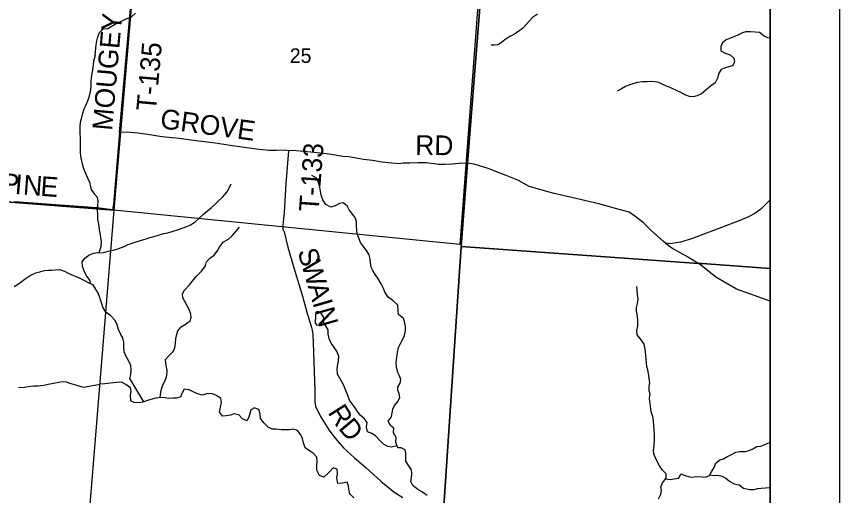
# Model space of a CAD drawing. Extents: x 0 to 42.5, y 0 to 22.
# Drawn here: x 7.815 to 9, y 18.727 to 19.417 of the extents above; entities that cross this region are included whole.
import ezdxf

# ---------------------------------------------------------------- set-up
doc = ezdxf.new("R2010")
doc.units = 0
for name, color, linetype in [('GM_X_County_Road', 7, 'Continuous'), ('GM_X_Interchange_Ramps', 7, 'Continuous'), ('GM_X_Minor_Lake', 7, 'Continuous'), ('GM_X_Minor_River', 7, 'Continuous'), ('GM_X_Section', 7, 'Continuous'), ('GM_X_Section_Text', 7, 'Continuous'), ('GM_X_Township_Road', 7, 'Continuous'), ('GM_X_Township_Road_Text', 7, 'Continuous'), ('SH_Cut_Line', 7, 'Continuous'), ('SH_Data', 7, 'Continuous')]:
    doc.layers.add(name, color=color, linetype=linetype)

msp = doc.modelspace()

# ---------------------------------------------------------------- linework, layer by layer
at = {"layer": 'GM_X_County_Road'}
msp.add_lwpolyline([(8.9, 19.0066), (8.8518, 19.0239), (8.8221, 19.0415), (8.7973, 19.0609)], dxfattribs=at)
at = {"layer": 'GM_X_Interchange_Ramps'}
msp.add_lwpolyline([(8.9, 19.0538), (8.9, 20.9), (8.5977, 20.9), (8.5975, 20.897), (8.533, 20.1102), (8.5155, 19.8538), (8.4644, 19.2057), (8.4553, 19.0856), (8.7971, 19.0612), (8.8021, 19.0608)], close=True, dxfattribs=at)
for points in [[(7.6874, 18.6472), (7.929, 18.6269), (8.111, 18.6109), (8.2565, 18.5997), (8.2741, 18.602), (8.283, 18.6019), (8.295, 18.5988), (8.3015, 18.5957), (8.4216, 18.5836), (8.4225, 18.5968), (8.4553, 19.0856), (8.4644, 19.2057), (8.5155, 19.8538)], [(8.9, 15.5376), (8.9, 19.0538), (8.8021, 19.0608), (8.7971, 19.0612), (8.4553, 19.0856), (8.4225, 18.5968), (8.4216, 18.5836), (8.4123, 18.4784), (8.3832, 18.1485), (8.3379, 17.6339), (8.308, 17.2922), (8.3087, 17.2846), (8.3084, 17.2765), (8.3074, 17.2694), (8.2902, 17.0877), (8.2877, 17.0646), (8.2823, 16.9912), (8.274, 16.8923), (8.2572, 16.7056), (8.248, 16.5943), (8.2478, 16.5901), (8.1793, 15.7911)]]:
    msp.add_lwpolyline(points, dxfattribs=at)
at = {"layer": 'GM_X_Minor_Lake'}
for points in [[(8.2566, 18.9794), (8.2574, 18.9834), (8.2557, 18.9861), (8.2525, 18.9908), (8.2482, 18.9918), (8.2459, 18.9907), (8.2455, 18.9863), (8.245, 18.9752), (8.2476, 18.9723), (8.2505, 18.9726), (8.2539, 18.9747)], [(8.2539, 18.9747), (8.2566, 18.9794)]]:
    msp.add_lwpolyline(points, dxfattribs=at)
at = {"layer": 'GM_X_Minor_River'}
for p, q in [((8.8752, 18.7939), (8.881, 18.7971)), ((8.881, 18.7971), (8.8865, 18.798)), ((8.8865, 18.798), (8.8917, 18.7997)), ((8.8917, 18.7997), (8.8966, 18.8019)), ((8.8966, 18.8019), (8.9, 18.8033)), ((8.8378, 18.7823), (8.8433, 18.7855)), ((8.8433, 18.7855), (8.8509, 18.7892)), ((8.8509, 18.7892), (8.8562, 18.79)), ((8.8562, 18.79), (8.8643, 18.7903)), ((8.8643, 18.7903), (8.87, 18.7916)), ((8.87, 18.7916), (8.8752, 18.7939)), ((8.8193, 18.7673), (8.822, 18.7734)), ((8.822, 18.7734), (8.8277, 18.7781)), ((8.8277, 18.7781), (8.833, 18.7794)), ((8.833, 18.7794), (8.8378, 18.7823)), ((8.8128, 18.7556), (8.8157, 18.7609)), ((8.8157, 18.7609), (8.8193, 18.7673)), ((8.7499, 18.7508), (8.7561, 18.7496)), ((8.7561, 18.7496), (8.7618, 18.7505)), ((8.7618, 18.7505), (8.7686, 18.7518)), ((8.7686, 18.7518), (8.7715, 18.7577)), ((8.7715, 18.7577), (8.7792, 18.755)), ((8.7792, 18.755), (8.7859, 18.7531)), ((8.7859, 18.7531), (8.7906, 18.7534)), ((8.7906, 18.7534), (8.7967, 18.754)), ((8.7967, 18.754), (8.8022, 18.7536)), ((8.8022, 18.7536), (8.8069, 18.7532)), ((8.8069, 18.7532), (8.8128, 18.7556)), ((8.8132, 18.7563), (8.8187, 18.7556)), ((8.8187, 18.7556), (8.8246, 18.7558)), ((8.8246, 18.7558), (8.8312, 18.7548)), ((8.8312, 18.7548), (8.8363, 18.7519)), ((8.8363, 18.7519), (8.8416, 18.7473)), ((8.8416, 18.7473), (8.8484, 18.7433)), ((8.8484, 18.7433), (8.8554, 18.742)), ((8.8554, 18.742), (8.8615, 18.7374)), ((8.8615, 18.7374), (8.8662, 18.7361)), ((8.8662, 18.7361), (8.8709, 18.7353)), ((8.8772, 18.7356), (8.8821, 18.7368)), ((8.8821, 18.7368), (8.8871, 18.7373)), ((8.8871, 18.7373), (8.8935, 18.7378)), ((8.8935, 18.7378), (8.8996, 18.7384)), ((8.8996, 18.7384), (8.9, 18.7384)), ((8.8709, 18.7353), (8.8772, 18.7356))]:
    msp.add_line(p, q, dxfattribs=at)
for points in [[(7.9283, 19.3609), (7.9297, 19.3759), (7.9307, 19.382), (7.9321, 19.3876), (7.9345, 19.3937), (7.9398, 19.3989), (7.9463, 19.3998), (7.9514, 19.4023), (7.957, 19.4058), (7.9617, 19.408), (7.968, 19.4112), (7.9737, 19.414), (7.9806, 19.4166), (7.9865, 19.4219)], [(8.5651, 19.4203), (8.5577, 19.4153), (8.5535, 19.4104), (8.5489, 19.4053), (8.5433, 19.3994), (8.5382, 19.3955), (8.5322, 19.3916), (8.5252, 19.388), (8.5181, 19.3832), (8.5134, 19.3796), (8.508, 19.3762), (8.5031, 19.3755), (8.4983, 19.3756)], [(8.9, 19.3857), (8.8968, 19.3859), (8.8917, 19.3886), (8.8846, 19.3938), (8.8783, 19.3944), (8.8715, 19.3946), (8.8651, 19.3947), (8.8601, 19.3932), (8.8536, 19.3899), (8.8479, 19.3874), (8.8414, 19.3852), (8.8367, 19.3832), (8.8313, 19.3791), (8.8292, 19.3734), (8.8289, 19.3673), (8.8354, 19.3638), (8.8424, 19.3617), (8.848, 19.3569), (8.8489, 19.3512), (8.846, 19.3459), (8.8405, 19.3445)], [(7.9283, 19.3609), (7.926, 19.3524), (7.9253, 19.3471), (7.9243, 19.3399), (7.9233, 19.3351), (7.9225, 19.3285), (7.9222, 19.3237), (7.9218, 19.3173), (7.9215, 19.311), (7.9207, 19.3057), (7.9193, 19.3008), (7.9173, 19.2947), (7.9142, 19.2883), (7.9121, 19.2832), (7.9097, 19.2756), (7.9079, 19.2695), (7.9067, 19.2641), (7.9061, 19.2589), (7.9064, 19.2515), (7.9066, 19.2394), (7.9066, 19.2327), (7.9067, 19.2266), (7.9068, 19.2213), (7.9073, 19.2156), (7.908, 19.2108), (7.9093, 19.2044), (7.9113, 19.1981), (7.9139, 19.1923), (7.9174, 19.1845), (7.9199, 19.1782), (7.9214, 19.1715), (7.9228, 19.1666), (7.9279, 19.1606)], [(8.8405, 19.3445), (8.8346, 19.3426), (8.8296, 19.3404), (8.826, 19.3351), (8.8242, 19.3279), (8.8207, 19.3211), (8.8143, 19.3166), (8.8076, 19.3106), (8.8014, 19.3054), (8.795, 19.3026), (8.7893, 19.3009), (8.7841, 19.3015), (8.7788, 19.3037), (8.7726, 19.3067), (8.766, 19.3098), (8.7581, 19.3135), (8.7509, 19.3166), (8.7458, 19.3189), (8.7397, 19.3216), (8.7339, 19.3228), (8.7284, 19.3231), (8.7223, 19.3229), (8.7162, 19.3226), (8.7092, 19.3217), (8.7039, 19.3204), (8.6966, 19.3177), (8.6919, 19.3158), (8.6862, 19.3128), (8.6797, 19.3091)], [(8.4061, 18.7266), (8.3995, 18.7316), (8.3929, 18.7356), (8.3857, 18.7412), (8.3829, 18.7471), (8.3835, 18.7522), (8.3844, 18.7579), (8.3835, 18.7639), (8.3801, 18.7693), (8.3756, 18.7762), (8.3757, 18.7826), (8.3757, 18.7875), (8.3744, 18.7923), (8.3689, 18.7952), (8.3638, 18.7956), (8.3611, 18.803), (8.3615, 18.8102), (8.3576, 18.8171), (8.3584, 18.8237), (8.3535, 18.8274), (8.3503, 18.8339), (8.3548, 18.8403), (8.3561, 18.8456), (8.3569, 18.8512), (8.3591, 18.8565), (8.3646, 18.8627), (8.3668, 18.8677), (8.3659, 18.8734), (8.3638, 18.8783), (8.3642, 18.883), (8.3675, 18.8887), (8.3683, 18.894), (8.3665, 18.8991), (8.3641, 18.9041), (8.362, 18.9121), (8.3617, 18.9176), (8.3623, 18.9227), (8.3631, 18.9284), (8.3636, 18.9331), (8.365, 18.9399), (8.3675, 18.9449), (8.3706, 18.9511), (8.3735, 18.9573), (8.375, 18.9643), (8.3751, 18.9694), (8.3742, 18.9755), (8.372, 18.9818), (8.3648, 18.9876), (8.3647, 18.9934), (8.3638, 19.0008), (8.3569, 19.0077), (8.3501, 19.0125), (8.3452, 19.0196), (8.3434, 19.0251), (8.34, 19.0316), (8.3353, 19.04), (8.3314, 19.0451), (8.3278, 19.0507), (8.3256, 19.0556), (8.3249, 19.0625), (8.3242, 19.0676), (8.3227, 19.0735), (8.3201, 19.0784), (8.3145, 19.0853), (8.3104, 19.0912), (8.3072, 19.099), (8.3057, 19.1043), (8.3048, 19.1091), (8.3045, 19.1148), (8.3044, 19.1211), (8.3033, 19.1262), (8.2992, 19.1317), (8.2941, 19.1384), (8.2913, 19.1439), (8.2855, 19.1485), (8.28, 19.1474), (8.2739, 19.1443), (8.2676, 19.1422), (8.2606, 19.1461), (8.2559, 19.1528), (8.2537, 19.1594), (8.2519, 19.1708), (8.2499, 19.1775), (8.2467, 19.184), (8.2403, 19.188)], [(7.9317, 19.0766), (7.9374, 19.0765), (7.9424, 19.0774), (7.949, 19.0791), (7.9561, 19.0805), (7.9622, 19.0824), (7.97, 19.0855), (7.9759, 19.0885), (7.9814, 19.0902), (7.9875, 19.0922), (7.9949, 19.0946), (8.0016, 19.0966), (8.0069, 19.0983), (8.0128, 19.1001), (8.0194, 19.102), (8.0272, 19.1042), (8.0329, 19.1053), (8.0407, 19.1075), (8.0466, 19.1095), (8.0533, 19.1117), (8.06, 19.1141), (8.0649, 19.1164), (8.072, 19.1208), (8.0773, 19.1257), (8.084, 19.1321), (8.0898, 19.137), (8.0951, 19.1411), (8.101, 19.1464), (8.1058, 19.1511), (8.112, 19.1569), (8.1177, 19.1637), (8.1219, 19.1703), (8.1239, 19.1756)], [(7.9338, 19.0766), (7.9344, 19.0784), (7.9369, 19.0856), (7.9374, 19.0925), (7.9365, 19.0978), (7.9358, 19.1027), (7.9347, 19.109), (7.9338, 19.1147), (7.9329, 19.12), (7.9322, 19.1247), (7.9319, 19.131), (7.9317, 19.1382), (7.9322, 19.1445), (7.9328, 19.1513), (7.9317, 19.156), (7.9279, 19.1606)], [(8.0219, 18.8679), (8.0223, 18.8719), (8.0235, 18.8785), (8.0248, 18.8834), (8.0268, 18.8883), (8.0293, 18.8934), (8.0316, 18.8995), (8.0319, 18.9061), (8.031, 18.9116), (8.0299, 18.9175), (8.0294, 18.9226), (8.0345, 18.9279), (8.0407, 18.9343), (8.0428, 18.9394), (8.0438, 18.946), (8.0446, 18.9523), (8.0454, 18.9574), (8.0474, 18.9642), (8.0522, 18.9698), (8.0598, 18.9747), (8.065, 18.9785), (8.0664, 18.9834), (8.066, 18.9881), (8.0636, 18.9948), (8.0603, 19.0011), (8.0573, 19.0064), (8.0543, 19.0114), (8.0538, 19.0173), (8.057, 19.0227), (8.0643, 19.0304), (8.0699, 19.0374), (8.0743, 19.0429), (8.082, 19.0502), (8.0873, 19.0575), (8.0885, 19.0636), (8.0935, 19.0689), (8.0994, 19.073), (8.105, 19.08), (8.1077, 19.0854), (8.1129, 19.092), (8.1201, 19.0959), (8.1257, 19.101), (8.1307, 19.107), (8.1362, 19.1134)], [(7.9217, 19.0319), (7.921, 19.0366), (7.9159, 19.0433), (7.9122, 19.0506), (7.9102, 19.0569), (7.9093, 19.0634), (7.9132, 19.0686), (7.9191, 19.0729), (7.9258, 19.0761), (7.9317, 19.0766)], [(7.8115, 19.028), (7.8166, 19.0307), (7.8214, 19.0343), (7.8275, 19.039), (7.8348, 19.0435), (7.8428, 19.0476), (7.8487, 19.049), (7.8555, 19.0507), (7.8606, 19.0512), (7.8658, 19.0515), (7.8707, 19.052), (7.8771, 19.0523), (7.8843, 19.0498), (7.8896, 19.0472), (7.8947, 19.0447), (7.8996, 19.0428), (7.9062, 19.0398), (7.913, 19.0363), (7.9192, 19.0332), (7.9243, 19.0305), (7.9284, 19.025)], [(7.9985, 18.8618), (7.9781, 18.8952), (7.9797, 18.9011), (7.9801, 18.9071), (7.9796, 18.9142), (7.9766, 18.9201), (7.9731, 18.9271), (7.9701, 18.9338), (7.9694, 18.9412), (7.9696, 18.9471), (7.9682, 18.9537), (7.9652, 18.9589), (7.9618, 18.9657), (7.96, 18.9724), (7.957, 18.9789), (7.9508, 18.9855), (7.9437, 18.9911), (7.9392, 18.998), (7.9377, 19.0029), (7.9359, 19.0088), (7.9344, 19.0136), (7.9314, 19.0204), (7.9282, 19.0252)], [(8.7217, 18.9234), (8.7212, 18.9284), (8.7208, 18.9339), (8.7199, 18.9399), (8.7189, 18.9449), (8.7144, 18.9508), (8.7088, 18.9584), (8.708, 18.9644), (8.7096, 18.9713), (8.7098, 18.9788), (8.7091, 18.9851), (8.7079, 18.9925), (8.7078, 18.9974), (8.7089, 19.0035), (8.7103, 19.0098), (8.7092, 19.0164), (8.7088, 19.0215), (8.7083, 19.0278)], [(8.3629, 18.7981), (8.3547, 18.7963), (8.3498, 18.7972), (8.3434, 18.8005), (8.3387, 18.8055), (8.3317, 18.8128), (8.3266, 18.8159), (8.3202, 18.8186), (8.3191, 18.8256), (8.3201, 18.8317), (8.3155, 18.8378), (8.3098, 18.8427), (8.3061, 18.8477), (8.3027, 18.8532), (8.2982, 18.859), (8.2944, 18.8641), (8.2919, 18.8708), (8.2887, 18.8792), (8.2867, 18.8843), (8.2837, 18.8896), (8.2809, 18.8948), (8.2773, 18.9016), (8.2768, 18.909), (8.2778, 18.9159), (8.2787, 18.9208), (8.2789, 18.9272), (8.2767, 18.9335), (8.2727, 18.9394), (8.2686, 18.9457), (8.2658, 18.9511), (8.2636, 18.9594), (8.2635, 18.9653), (8.256, 18.9784)], [(8.7395, 18.7221), (8.7429, 18.7284), (8.7437, 18.7337), (8.7426, 18.7394), (8.7451, 18.7452), (8.7506, 18.7517), (8.7506, 18.7581), (8.7451, 18.7633), (8.741, 18.7693), (8.7372, 18.7756), (8.735, 18.7809), (8.7327, 18.7868), (8.732, 18.7921), (8.733, 18.7988), (8.7338, 18.8067), (8.7334, 18.8139), (8.7331, 18.821), (8.7325, 18.8276), (8.732, 18.8337), (8.731, 18.8405), (8.7295, 18.8456), (8.7284, 18.8504), (8.7279, 18.8566), (8.7268, 18.8621), (8.7262, 18.8671), (8.7272, 18.8726), (8.7261, 18.8777), (8.7261, 18.884), (8.7269, 18.8889), (8.726, 18.8957), (8.7248, 18.9024), (8.7239, 18.9077), (8.7226, 18.9124), (8.7221, 18.9173), (8.7217, 18.9234)], [(7.8181, 18.8821), (7.8261, 18.883), (7.8322, 18.8837), (7.8394, 18.8846), (7.8462, 18.8849), (7.8542, 18.8859), (7.8604, 18.8872), (7.866, 18.8883), (7.8707, 18.8892), (7.876, 18.8902), (7.8812, 18.8909), (7.8865, 18.8907), (7.8934, 18.8883), (7.9001, 18.8862), (7.9074, 18.8838), (7.9125, 18.883), (7.9192, 18.8841), (7.9353, 18.8872)], [(7.9985, 18.8618), (7.9922, 18.86), (7.9846, 18.8606), (7.9797, 18.8633), (7.979, 18.8711), (7.9802, 18.8764), (7.9793, 18.8819), (7.9725, 18.8865), (7.9661, 18.8898), (7.9594, 18.8897), (7.9545, 18.889), (7.9467, 18.8881), (7.942, 18.8878), (7.9353, 18.8872)], [(8.3009, 18.7233), (8.2947, 18.7289), (8.2935, 18.7359), (8.2928, 18.7407), (8.2909, 18.746), (8.2844, 18.7445), (8.2778, 18.7442), (8.2763, 18.7516), (8.2774, 18.7581), (8.2768, 18.7647), (8.2708, 18.7668), (8.2647, 18.7597), (8.2576, 18.7531), (8.2511, 18.7554), (8.2472, 18.7633), (8.2473, 18.7699), (8.2481, 18.7762), (8.2476, 18.7818), (8.2425, 18.7872), (8.2367, 18.791), (8.2305, 18.7955), (8.2281, 18.8025), (8.2268, 18.8088), (8.2246, 18.8139), (8.2195, 18.8204), (8.2132, 18.8222), (8.2079, 18.8215), (8.2024, 18.8213), (8.1965, 18.8214), (8.1884, 18.8222), (8.1833, 18.8223), (8.1772, 18.8251), (8.1716, 18.8311), (8.1663, 18.8378), (8.1658, 18.844), (8.1646, 18.8503), (8.1576, 18.853), (8.1526, 18.85), (8.1508, 18.8451), (8.1497, 18.8396), (8.1464, 18.8343), (8.1402, 18.8372), (8.1351, 18.843), (8.1285, 18.8444), (8.1233, 18.8427), (8.117, 18.8414), (8.1117, 18.8411), (8.1072, 18.847), (8.1086, 18.8542), (8.11, 18.8608), (8.1091, 18.8667), (8.1029, 18.871), (8.0972, 18.8733), (8.09, 18.8735), (8.0828, 18.8715), (8.0754, 18.8733), (8.0694, 18.8762), (8.0637, 18.8789), (8.0563, 18.8797), (8.0528, 18.8739), (8.0513, 18.8686), (8.0454, 18.8669), (8.0406, 18.8668), (8.0342, 18.8666), (8.0289, 18.8674), (8.023, 18.8681), (8.0154, 18.8668), (8.0085, 18.8652), (8.0036, 18.8637), (7.9985, 18.8618)]]:
    msp.add_lwpolyline(points, dxfattribs=at)
at = {"layer": 'GM_X_Section'}
for points in [[(7.488, 19.687), (7.9983, 19.6419), (7.955, 19.138), (7.4474, 19.1773)], [(7.9983, 19.6419), (8.4918, 19.5993), (8.4533, 19.0885), (7.955, 19.138)], [(7.4474, 19.1773), (7.955, 19.138), (7.9137, 18.631), (7.4421, 18.6691), (7.4064, 18.6718)]]:
    msp.add_lwpolyline(points, close=True, dxfattribs=at)
at = {"layer": 'GM_X_Township_Road'}
for points in [[(7.9634, 19.2495), (7.9759, 19.3905), (7.9849, 19.4927), (7.993, 19.5825), (7.9965, 19.6227), (7.9981, 19.6409)], [(7.9634, 19.2495), (7.9545, 19.1463), (7.9531, 19.1383), (7.9307, 19.1414), (7.8119, 19.15)], [(8.2067, 19.2234), (8.2023, 19.2243), (8.1894, 19.2236), (8.1781, 19.2236), (8.1599, 19.2259), (8.1258, 19.2304), (8.1008, 19.2342), (8.0697, 19.238), (8.0492, 19.241), (8.0242, 19.2433), (8.0068, 19.2463), (7.9901, 19.2486), (7.9734, 19.2501), (7.9634, 19.2495)], [(8.2067, 19.2234), (8.203, 19.1756), (8.2003, 19.1351), (8.1984, 19.1158), (8.1984, 19.1103), (8.2003, 19.1066), (8.2058, 19.0845), (8.215, 19.0532), (8.227, 19.0137), (8.2334, 18.9888), (8.2371, 18.9769), (8.2398, 18.9686), (8.2408, 18.9649), (8.2417, 18.9585), (8.2426, 18.9336), (8.2435, 18.9051), (8.2444, 18.8775), (8.2444, 18.8619), (8.2454, 18.8554), (8.2527, 18.8407), (8.2647, 18.8214), (8.2739, 18.8094), (8.2858, 18.7956), (8.3015, 18.7809), (8.318, 18.7671), (8.3401, 18.7469), (8.3585, 18.7322), (8.3714, 18.7239)], [(8.5378, 19.1805), (8.5369, 19.181), (8.5199, 19.1876), (8.494, 19.1977), (8.474, 19.2043), (8.4645, 19.2054), (8.4519, 19.2049), (8.4422, 19.2042), (8.4318, 19.2034), (8.4233, 19.2036), (8.4049, 19.2061), (8.3933, 19.2061), (8.3812, 19.2054), (8.3713, 19.2054), (8.3653, 19.2046), (8.3554, 19.2054), (8.341, 19.2069), (8.3274, 19.2092), (8.3145, 19.2107), (8.2933, 19.2145), (8.2849, 19.2152), (8.2652, 19.2183), (8.2387, 19.2213), (8.2235, 19.2228), (8.2122, 19.2236), (8.2067, 19.2234)], [(8.7496, 19.0903), (8.7461, 19.0931), (8.7294, 19.1079), (8.7174, 19.1201), (8.7053, 19.1294), (8.6969, 19.1348), (8.6828, 19.139), (8.6534, 19.1469), (8.5873, 19.1622), (8.5532, 19.172), (8.5378, 19.1805)], [(8.9, 19.1531), (8.8994, 19.1524), (8.8925, 19.1449), (8.8869, 19.1394), (8.8781, 19.1328), (8.8691, 19.1281), (8.8565, 19.1228), (8.834, 19.1145), (8.7867, 19.0964), (8.7708, 19.0919), (8.7562, 19.0894), (8.7496, 19.0903)], [(8.7496, 19.0903), (8.7602, 19.0827), (8.7702, 19.0768), (8.7825, 19.07), (8.7973, 19.0609)]]:
    msp.add_lwpolyline(points, dxfattribs=at)
at = {"layer": 'SH_Cut_Line'}
for points in [[(7.6874, 18.6472), (7.929, 18.6269), (8.111, 18.6109), (8.2565, 18.5997), (8.2741, 18.602), (8.283, 18.6019), (8.295, 18.5988), (8.3015, 18.5957), (8.4216, 18.5836), (8.4225, 18.5968), (8.4553, 19.0856), (8.7971, 19.0612), (8.8021, 19.0608), (8.9, 19.0538), (8.9, 20.9)], [(8.9, 14.1), (8.9, 19.0538), (8.8021, 19.0608), (8.7971, 19.0612), (8.4553, 19.0856), (8.4225, 18.5968), (8.4216, 18.5836), (8.4123, 18.4784), (8.3832, 18.1485), (8.3379, 17.6339), (8.308, 17.2922), (8.3087, 17.2846), (8.3084, 17.2765), (8.3074, 17.2694), (8.2902, 17.0877), (8.2877, 17.0646), (8.2823, 16.9912), (8.274, 16.8923), (8.2572, 16.7056), (8.248, 16.5943), (8.2478, 16.5901), (8.1793, 15.7911)]]:
    msp.add_lwpolyline(points, dxfattribs=at)
at = {"layer": 'SH_Data'}
for p, q in [((9, 21), (9, 14)), ((8.9, 20.9), (8.9, 14.1))]:
    msp.add_line(p, q, dxfattribs=at)

# ---------------------------------------------------------------- texts
at = {"layer": 'GM_X_Section_Text'}
msp.add_text('25', height=0.02093, rotation=0, dxfattribs=at).set_placement((8.2085, 19.35))
at = {"layer": 'GM_X_Township_Road_Text'}
for s, height, rotation, p in [('MOUGEY', 0.02841, 84.9757, (7.9525, 19.2518)), ('T-135', 0.02841, 84.9571, (8.0157, 19.2798)), ('GROVE', 0.02841, 352.2615, (8.0207, 19.2561)), ('RD', 0.02841, 359.5069, (8.389, 19.2174)), ('T-133', 0.02841, 85.7948, (8.2499, 19.1347)), ('P', 0.0284, 353.749, (7.7921, 19.1636)), ('I', 0.0284, 355.0281, (7.8118, 19.1614)), ('N', 0.0284, 355.7382, (7.8238, 19.1604)), ('E', 0.0284, 355.8551, (7.8488, 19.1585)), ('S', 0.0284, 286.3279, (8.2194, 19.0786)), ('W', 0.0284, 286.3297, (8.2248, 19.0602)), ('A', 0.0284, 286.3282, (8.234, 19.0287)), ('I', 0.0284, 286.3153, (8.241, 19.0047)), ('N', 0.0284, 285.9339, (8.2443, 18.9935)), ('R', 0.0284, 302.2849, (8.2625, 18.8464)), ('D', 0.0284, 310.0371, (8.2774, 18.8233))]:
    msp.add_text(s, height=height, rotation=rotation, dxfattribs=at).set_placement(p)

doc.saveas('drawing.dxf')
